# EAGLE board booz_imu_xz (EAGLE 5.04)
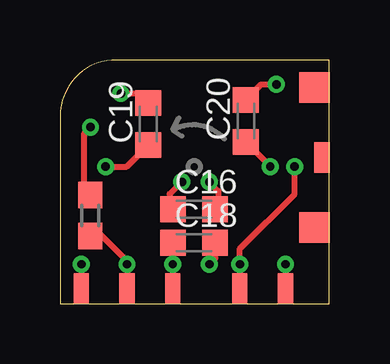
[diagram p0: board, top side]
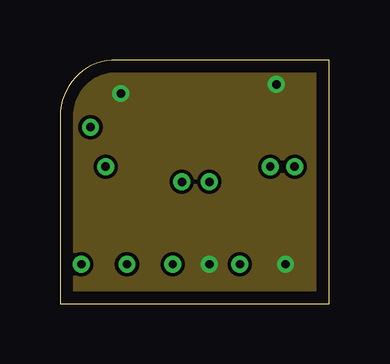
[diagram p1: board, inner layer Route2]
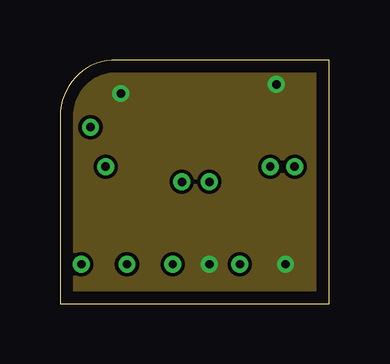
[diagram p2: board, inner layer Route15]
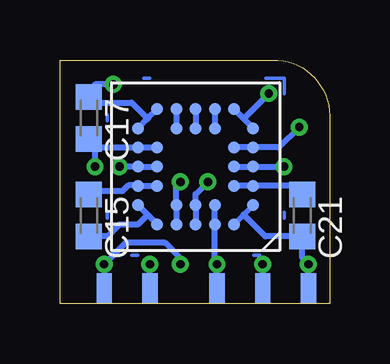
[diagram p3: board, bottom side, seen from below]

Size 11.23 x 10.16 mm. Coordinates in mm from the lower left corner, seen from the top.
Outline: 11.23,10.15 11.23,0 0.01,0 0.01,7.62 arc-90 2.16,10.16 11.21,10.16
Copper layers (1*2+15*16): Top 0.035mm / dielectric 0.2mm / Route2 0.035mm / dielectric 1.5mm / Route15 0.035mm / dielectric 0.2mm / Bottom 0.035mm
Design rules "eurocircuits_verified_4l": minimum track width 0.15mm, minimum drill 0.35mm, track to track 0.15mm, track to pad 0.15mm, pad to pad 0.15mm, via to via 0.15mm, smd to smd 0.15mm, copper to edge 20mil, drill to drill 8mil, minimum pad ring 0.177mm, minimum via ring 0.177mm, stop-mask expansion 4mil, vias tented up to drill 14mil, thermal gap 10mil

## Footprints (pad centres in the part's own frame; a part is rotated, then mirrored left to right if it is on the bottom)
C0603K = smd 1.05 x 1.08: 1 -0.875,0; 2 0.875,0
BC-32 = smd 0.5 x 0.5: A2 -1.6,2.4; A3 -0.8,2.4; A4 0,2.4; A5 0.8,2.4; A6 1.6,2.4; B1 -2.4,1.6; B3 -0.8,1.6; B4 0,1.6; B5 0.8,1.6; B7 2.4,1.6; C1 -2.4,0.8; C2 -1.6,0.8; C6 1.6,0.8; C7 2.4,0.8; D1 -2.4,0; D2 -1.6,0; D6 1.6,0; D7 2.4,0; E1 -2.4,-0.8; E2 -1.6,-0.8; E6 1.6,-0.8; E7 2.4,-0.8; F1 -2.4,-1.6; F3 -0.8,-1.6; F4 0,-1.6; F5 0.8,-1.6; F7 2.4,-1.6; G2 -1.6,-2.4; G3 -0.8,-2.4; G4 0,-2.4; G5 0.8,-2.4; G6 1.6,-2.4
R0603 = smd 1.1 x 1: 1 -0.85,0; 2 0.85,0
SOLDER_PAD = smd 0.635 x 1.27: P$1 0,0

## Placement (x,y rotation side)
C15  22nF  [C0603K]  10.03,3.68 270 bottom
C16  22nF  [C0603K]  5.59,3.94 0 top
C17  100nF  [C0603K]  10.03,7.75 270 bottom
C18  100nF  [C0603K]  5.59,2.54 0 top
C19  100nF  [C0603K]  3.68,7.49 90 top
C20  47nF  [C0603K]  7.75,7.62 90 top
C21  22nF  [C0603K]  1.14,3.68 270 bottom
GYRO_X  ADXR  [BC-32]  5.59,5.72 180 bottom
R1  0/DNP  [R0603]  1.27,3.68 270 top
U$1  SOLDER_PAD  [SOLDER_PAD]  7.49,0.64 180 top
U$2  SOLDER_PAD  [SOLDER_PAD]  9.4,0.64 180 top
U$3  SOLDER_PAD  [SOLDER_PAD]  4.7,0.64 180 top
U$4  SOLDER_PAD  [SOLDER_PAD]  2.79,0.64 180 top
U$5  SOLDER_PAD  [SOLDER_PAD]  0.89,0.64 180 top
U$6  SOLDER_PAD  [SOLDER_PAD]  10.29,9.02 0 top
U$8  SOLDER_PAD  [SOLDER_PAD]  0.89,0.64 0 bottom
U$9  SOLDER_PAD  [SOLDER_PAD]  2.79,0.64 0 bottom
U$10  SOLDER_PAD  [SOLDER_PAD]  4.7,0.64 0 bottom
U$11  SOLDER_PAD  [SOLDER_PAD]  7.49,0.64 0 bottom
U$12  SOLDER_PAD  [SOLDER_PAD]  9.4,0.64 0 bottom
U$13  SOLDER_PAD  [SOLDER_PAD]  10.92,9.02 0 top
U$14  SOLDER_PAD  [SOLDER_PAD]  10.92,6.1 0 top
U$15  SOLDER_PAD  [SOLDER_PAD]  10.92,3.17 0 top
U$16  SOLDER_PAD  [SOLDER_PAD]  10.29,3.17 0 top

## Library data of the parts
C15-C21 R1 = rcl
GYRO_X U$1-U$6 U$8-U$16 = paparazzi

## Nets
+5V: C17.2 GYRO_X.E6 GYRO_X.E7 U$1.P$1 U$11.P$1
+5VA: C18.1 GYRO_X.A3 GYRO_X.B3 U$3.P$1 U$10.P$1
GND: C17.1 C18.2 C19.2 C20.2 GYRO_X.F1 GYRO_X.F7 GYRO_X.G2 GYRO_X.G6 U$2.P$1 U$12.P$1
N$6: C21.1 GYRO_X.C1 GYRO_X.C2
N$7: C15.1 GYRO_X.C6 GYRO_X.C7
N$11: C20.1 GYRO_X.D6 GYRO_X.D7
N$12: C16.2 GYRO_X.A5 GYRO_X.B5
N$13: C16.1 GYRO_X.A4 GYRO_X.B4
N$14: C15.2 GYRO_X.A6 GYRO_X.B7
N$17: GYRO_X.E1 GYRO_X.E2 R1.1
N$19: C19.1 GYRO_X.D1 GYRO_X.D2
RATE_X: C21.2 GYRO_X.A2 GYRO_X.B1 U$5.P$1 U$8.P$1
ST1: GYRO_X.F5 GYRO_X.G5
ST2: GYRO_X.F4 GYRO_X.G4
TEMP_X: GYRO_X.F3 GYRO_X.G3
VREF: R1.2 U$4.P$1 U$9.P$1

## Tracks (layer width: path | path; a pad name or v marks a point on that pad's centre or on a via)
+5V  (via drill 0.35)
  Top 0.254: U$11.P$1 v7.49,1.65 7.49,2.29 9.78,4.57 v9.78,5.72
  Bottom 0.254: U$11.P$1 v7.49,1.65 | C17.2 10.03,6.86 9.69,6.51 9.65,6.51 | 9.65,6.51 GYRO_X.E7 7.99,6.49 | 9.65,6.51 9.65,6.48 9.78,6.35 v9.78,5.72 | 7.99,6.49 8,6.48 | GYRO_X.E6 7.96,6.51 7.99,6.49
+5VA  (via drill 0.35)
  Top 0.254: U$10.P$1 v4.7,1.65 C18.1
  Bottom 0.203: 4.81,3.32 4.82,3.3 | GYRO_X.A3 4.81,3.32 | 4.81,3.32 4.79,3.34
  Bottom 0.254: U$10.P$1 v4.7,1.65 4.79,1.74 GYRO_X.A3 | 4.79,3.34 GYRO_X.B3
GND  (via drill 0.35)
  Top 0.254: v9.4,1.65 U$12.P$1 | C19.2 3.68,8.38 3.3,8.76 v2.54,8.76 | C20.2 8.39,9.14 v9.02,9.14 | C18.2 6.48,2.54 6.48,1.91 v6.22,1.65
  Bottom 0.203: GYRO_X.F7 8,7.33 8,7.37 7.94,7.37 | GYRO_X.F1 3.17,7.32 | GYRO_X.F1 | GYRO_X.F1
  Bottom 0.254: U$12.P$1 v9.4,1.65 8.51,2.54 6.86,2.54 6.22,1.91 v6.22,1.65 | 3.59,7.72 GYRO_X.G2 | 3.59,7.72 GYRO_X.F1 | v2.54,8.76 3.59,7.72 | 7.62,7.75 8.25,8.38 9.92,8.38 C17.1 10.03,8.89 9.78,9.14 v9.02,9.14 | GYRO_X.G6 7.55,7.75 7.62,7.75 | 7.94,7.37 7.62,7.68 7.62,7.75
  pour Route2: 11.17,10.03 0.13,10.03 0.13,0.13 11.17,0.13
  pour Route15: 0.13,0.13 11.17,0.13 11.17,10.03 0.13,10.03
N$1
  Bottom 0.152: 2.67,9.4 1.9,9.4 1.9,8.76
N$2
  Bottom 0.152: 7.75,9.4 7.49,9.4
N$3
  Bottom 0.152: 9.27,7.62 9.27,7.87
N$4
  Bottom 0.152: 9.27,3.56 9.27,3.81
N$5
  Bottom 0.152: 1.9,3.81 1.9,3.56
N$6
  Bottom 0.203: GYRO_X.C1 3.17,4.92 3.17,4.95
  Bottom 0.254: GYRO_X.C2 GYRO_X.C1 2.12,4.92 1.48,4.92 1.14,4.57 C21.1
N$7
  Bottom 0.203: 7.99,4.94 8,4.95 | GYRO_X.C7 7.99,4.94 | 7.99,4.94 7.96,4.92 | C15.1 9.9,4.57
  Bottom 0.254: 7.96,4.92 GYRO_X.C6 | 7.99,4.94 8.39,4.94 8.63,4.7 9.9,4.7 10.03,4.57 C15.1
N$8
  Bottom 0.152: 3.17,2.03 2.92,2.03
N$9
  Bottom 0.152: 8.25,2.03 8,2.03
N$11  (via drill 0.35)
  Top 0.254: C20.1 8.76,5.73 v8.76,5.72
  Bottom 0.254: GYRO_X.D6 GYRO_X.D7 v8.76,5.72
N$12  (via drill 0.35)
  Top 0.254: C16.2 6.6,3.94 6.6,4.7 v6.22,5.08
  Bottom 0.203: 6.36,3.32 6.35,3.3 | 6.36,3.32 GYRO_X.A5 | 6.39,3.34 6.36,3.32
  Bottom 0.254: 6.39,3.34 GYRO_X.B5 6.39,4.92 v6.22,5.08
N$13  (via drill 0.35)
  Top 0.254: C16.1 4.57,3.94 4.57,4.57 v5.08,5.08
  Bottom 0.203: GYRO_X.A4 5.59,3.3
  Bottom 0.254: GYRO_X.A4 GYRO_X.B4 5.59,4.57 v5.08,5.08
N$14
  Bottom 0.203: GYRO_X.B7 8,4.1 8,4.06 7.94,4.06
  Bottom 0.254: 7.94,4.06 7.59,3.71 | 7.59,3.71 GYRO_X.A6 | C15.2 9.26,2.81 8.76,3.3 8,3.3 7.59,3.71
N$17  (via drill 0.35)
  Top 0.254: R1.1 1.1,4.7 1.01,4.7 1.01,7.11 v1.27,7.37
  Bottom 0.203: GYRO_X.E2 4.02,6.51 4.06,6.48 | 2.12,6.51 2.16,6.51
  Bottom 0.254: 4.02,6.51 GYRO_X.E1 2.16,6.51 | v1.27,7.37 2.12,6.51
N$19  (via drill 0.35)
  Top 0.254: C19.1 2.78,5.72 v1.9,5.72
  Bottom 0.203: GYRO_X.D1 3.17,5.72 | v1.9,5.72 2.03,5.72
  Bottom 0.254: GYRO_X.D2 GYRO_X.D1 v1.9,5.72
RATE_X  (via drill 0.35)
  Top 0.254: v0.89,1.65 U$8.P$1
  Bottom 0.203: GYRO_X.A2 3.97,3.3 3.94,3.3 3.94,3.37 3.59,3.71 GYRO_X.B1
  Bottom 0.254: U$8.P$1 v0.89,1.65 1.14,1.91 C21.2 | C21.2 2.68,2.81 3.59,3.71 | C21.2 1.14,2.92
ST1
  Bottom 0.203: 6.36,8.11 6.35,8.13 | GYRO_X.G5 6.36,8.11 | 6.36,8.11 6.39,8.09
  Bottom 0.254: 6.39,8.09 GYRO_X.F5
ST2
  Bottom 0.203: GYRO_X.G4 5.59,8.13
  Bottom 0.254: GYRO_X.G4 GYRO_X.F4
TEMP_X
  Bottom 0.203: 4.81,8.11 4.82,8.13 | GYRO_X.G3 4.81,8.11 | 4.81,8.11 4.79,8.09
  Bottom 0.254: 4.79,8.09 GYRO_X.F3
VREF  (via drill 0.35)
  Top 0.203: R1.2 1.27,2.79
  Top 0.254: U$9.P$1 v2.79,1.65 2.79,1.78 1.65,2.92 1.56,2.83 R1.2
  Bottom 0.254: v2.79,1.65 U$9.P$1

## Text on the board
tDocu: p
